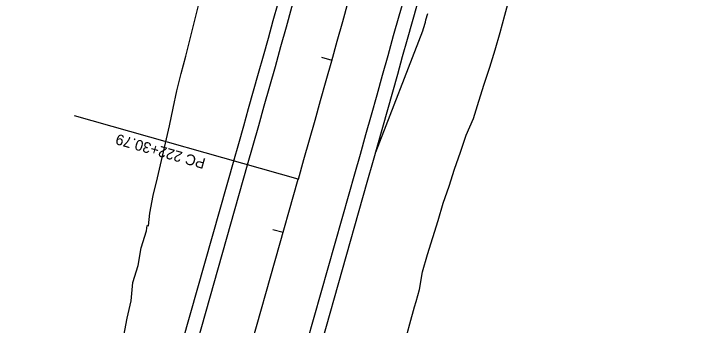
# Model space of a CAD drawing. Extents: x 1441466 to 1476381, y 2042742 to 2057194.
# Drawn here: x 1445850.5 to 1446227, y 2055080.6 to 2055255 of the extents above; entities that cross this region are included whole.
import ezdxf

# ---------------------------------------------------------------- set-up
doc = ezdxf.new("R2010")
doc.units = 0
for name, color, linetype in [('R_Horz Alg', 7, 'Continuous'), ('R_Horz Alg Annot', 7, 'Continuous'), ('R_Horz Alg Stationing', 7, 'Continuous'), ('R_Proposed Const Limits', 7, 'Continuous'), ('R_Proposed Road', 7, 'Continuous'), ('R_Shld', 7, 'Continuous')]:
    doc.layers.add(name, color=color, linetype=linetype)

msp = doc.modelspace()

# ---------------------------------------------------------------- linework, layer by layer
at = {"layer": 'R_Horz Alg'}
msp.add_line((1445886.03, 2054726.64), (1446009.58, 2055162.32), dxfattribs=at)
msp.add_arc((1423960.81, 2061415.35), 22918.31, 344.166667, 346, dxfattribs=at)
at = {"layer": 'R_Horz Alg Annot'}
msp.add_lwpolyline([(1446009.58, 2055162.32), (1445884.52, 2055197.79)], dxfattribs=at)
at = {"layer": 'R_Horz Alg Stationing'}
for points in [[(1446022.59, 2055230.55), (1446028.37, 2055228.93)], [(1445995.41, 2055134.34), (1446001.18, 2055132.7)]]:
    msp.add_lwpolyline(points, dxfattribs=at)
at = {"layer": 'R_Proposed Const Limits'}
for points in [[(1446069.18, 2055071.84), (1446071.85, 2055081.48), (1446074.52, 2055091.11), (1446075.33, 2055093.92), (1446075.33, 2055093.93), (1446077.3, 2055100.72), (1446078.9, 2055110.66), (1446081.69, 2055120.26), (1446084.68, 2055129.81), (1446087.72, 2055139.34), (1446090.57, 2055148.96), (1446093.92, 2055158.44), (1446096.89, 2055168.03), (1446100.12, 2055177.55), (1446103.37, 2055187.06), (1446107.38, 2055196.36), (1446110.42, 2055205.93), (1446113.47, 2055215.5), (1446116.53, 2055225.06), (1446119.59, 2055234.63), (1446122.28, 2055244.3), (1446124.87, 2055254), (1446127.46, 2055263.7)], [(1445912.17, 2055074.79), (1445913.89, 2055084.69), (1445916.13, 2055094.45), (1445917.2, 2055104.54), (1445920.13, 2055114.11), (1445921.88, 2055124.01), (1445924.7, 2055133.6), (1445925.09, 2055136.53), (1445925.83, 2055136.33), (1445926.59, 2055143.46), (1445928.53, 2055153.3), (1445930.86, 2055163.04), (1445933.11, 2055172.79), (1445935.43, 2055182.53), (1445937.57, 2055192.28), (1445939.74, 2055202.03), (1445941.77, 2055211.81), (1445944.09, 2055221.51), (1445946.66, 2055231.14), (1445949.22, 2055240.77), (1445951.61, 2055250.45), (1445953.93, 2055260.15)]]:
    msp.add_lwpolyline(points, dxfattribs=at)
at = {"layer": 'R_Proposed Road'}
for p, q in [((1445850.48, 2054738.8), (1445974.04, 2055174.48)), ((1445857.64, 2054734.69), (1445981.2, 2055170.37)), ((1445914.41, 2054718.59), (1446037.96, 2055154.27)), ((1445922.1, 2054716.41), (1446045.66, 2055152.09))]:
    msp.add_line(p, q, dxfattribs=at)
for radius, end in [(22888.81, 346), (22947.81, 346), (22880.81, 344.983157), (22955.81, 344.983722)]:
    msp.add_arc((1423960.81, 2061415.35), radius, 344.166667, end, dxfattribs=at)
at = {"layer": 'R_Shld'}
msp.add_line((1446052.86, 2055177.53), (1446079.18, 2055245.35), dxfattribs=at)
msp.add_arc((1423960.29, 2061413.42), 22962.81, 344.41834, 344.44334, dxfattribs=at)

# ---------------------------------------------------------------- texts
at = {"layer": 'R_Horz Alg Annot'}
msp.add_text('PC 222+30.79', height=6, rotation=164.1667, dxfattribs=at).set_placement((1445958.19, 2055173.78))

doc.saveas('drawing.dxf')
